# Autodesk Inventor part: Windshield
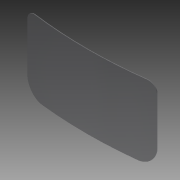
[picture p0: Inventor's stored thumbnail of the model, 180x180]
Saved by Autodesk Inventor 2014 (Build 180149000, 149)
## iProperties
Created: 2006-03
Part Number: Windshield
Document SubType Name: Modeling
Designer: Autodesk, Inc.
Mass: 21946 g
Surface Area: 25523.6 cm^2
Volume: 10067 cm^3
Density: 2.18 g/cm^3
Material: Glass
Appearance: Light Gray
Author: Autodesk, Inc.
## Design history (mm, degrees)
sketch "Sketch1"
  geometry: L1 (0, 5943.43)-(0, -1056.57) reference; L2 (-1050, 0)-(1050, 0) reference; A1 r 5000 centre (0, 4943.43) between (-750, 0) and (750, 0); 1 further point
  constraints: 3 point on line, 2 point on circle, 1 centre point
  dimensions: "d0" = 1500 distance of A1.end A1.start; "d2" = 5000 radius of A1
workplane "Work Plane1"
sketch "Sketch2"
  geometry: L1 (-4, 425)-(4, 425); L2 (4, 425)-(4, -425); L3 (4, -425)-(-4, -425); L4 (-4, -425)-(-4, 425); L5 (-4, 425)-(4, -425); 3 further points
  constraints: 10 end point, 2 parallel, 1 coincident, 1 horizontal, 1 midpoint, 1 perpendicular
  dimensions: "d3" = 8 distance of L1.start L1.end; "d4" = 850 distance of L1.end L2.end
sweep "Sweep1" sketch "Sketch2" dims "d5" = 0
fillet "Fillet1" dims "d6" = 100
fillet "Fillet2" dims "d7" = 200
body "Solid1"
